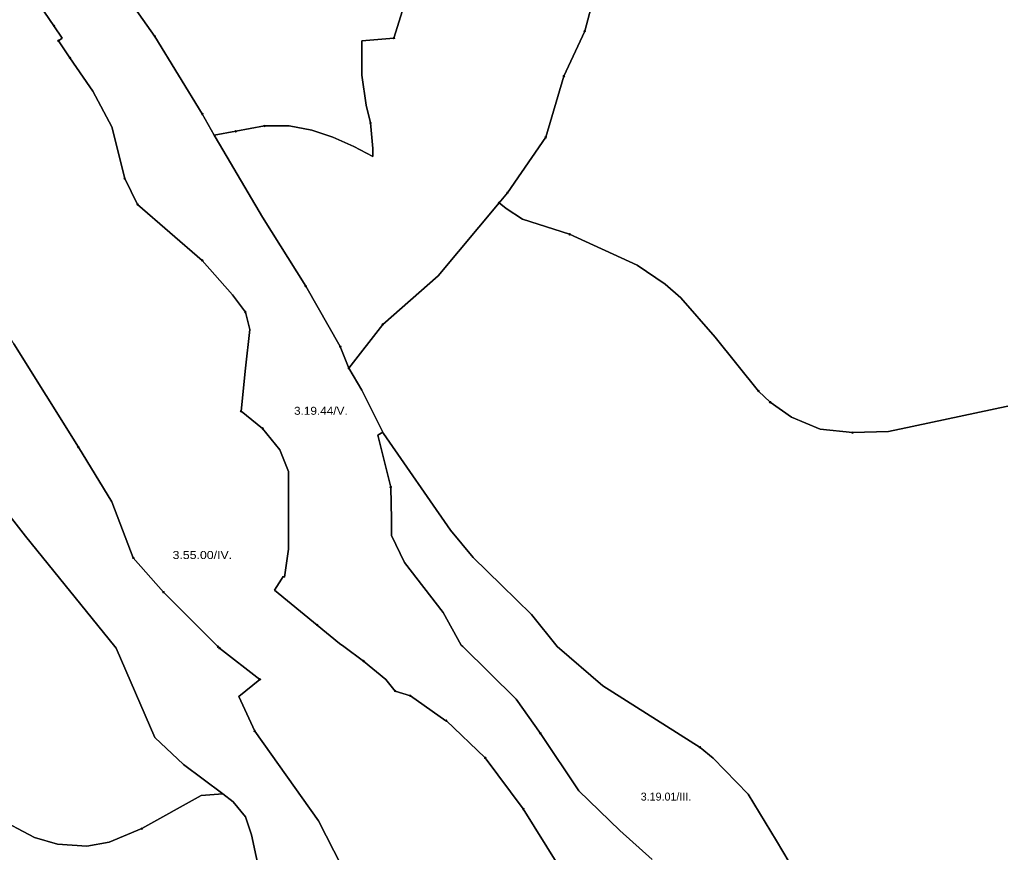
# Model space of a CAD drawing. Extents: x -650455 to -642254, y -1075222 to -1066610.
# Drawn here: x -646878 to -645652, y -1072257 to -1071216 of the extents above; entities that cross this region are included whole.
import ezdxf
from ezdxf.enums import TextEntityAlignment as Align

# ---------------------------------------------------------------- set-up
doc = ezdxf.new("R2010")
doc.units = 0
doc.header["$LTSCALE"] = 4
doc.header["$PDMODE"] = 32
doc.header["$PDSIZE"] = 2
for name, color, linetype, lineweight in [('1', 7, 'Continuous', 25), ('11', 7, 'Continuous', 13), ('12', 7, 'Continuous', 13), ('13', 7, 'Continuous', 13), ('14', 7, 'Continuous', 13), ('15', 7, 'Continuous', 13)]:
    doc.layers.add(name, color=color, linetype=linetype, lineweight=lineweight)
doc.layers.add('2', color=7, linetype='Continuous')

msp = doc.modelspace()

# ---------------------------------------------------------------- linework, layer by layer
at = {"layer": '1'}
for points in [[(-646154.372, -1071165.527), (-646171.706, -1071230.527), (-646197.706, -1071286.861), (-646220.456, -1071363.237), (-646268.124, -1071432.571), (-646278.639, -1071445.19), (-646354.791, -1071536.572), (-646424.125, -1071597.24), (-646466.433, -1071651.884), (-646477.206, -1071624.953), (-646520.295, -1071549.547), (-646574.157, -1071463.368), (-646628.018, -1071371.803), (-646634.506, -1071360.45), (-646607.539, -1071355.754), (-646571.854, -1071349.129), (-646541.062, -1071349.053), (-646512.831, -1071354.248), (-646486.255, -1071363.056), (-646460.282, -1071374.876)], [(-646190.5, -1071484.501), (-646249.5, -1071465.5), (-646270, -1071452.5), (-646278.639, -1071445.19), (-646268.124, -1071432.571), (-646220.456, -1071363.237), (-646197.706, -1071286.861), (-646171.706, -1071230.527), (-646154.372, -1071165.527)], [(-646393.156, -1071184.317), (-646410.042, -1071239.194), (-646450.275, -1071242.536), (-646450.275, -1071285.625), (-646444.889, -1071323.328), (-646439.373, -1071345.392), (-646436.341, -1071377.436), (-646436.341, -1071387.223), (-646460.282, -1071374.876), (-646486.255, -1071363.056), (-646512.831, -1071354.248), (-646541.062, -1071349.053), (-646571.854, -1071349.129), (-646607.539, -1071355.754), (-646634.506, -1071360.45), (-646649.563, -1071334.1), (-646708.811, -1071237.149), (-646743.712, -1071187.194)], [(-646743.712, -1071187.194), (-646708.811, -1071237.149), (-646649.563, -1071334.1), (-646634.506, -1071360.45), (-646628.018, -1071371.803), (-646574.157, -1071463.368), (-646520.295, -1071549.547), (-646477.206, -1071624.953), (-646466.433, -1071651.884), (-646450.126, -1071679.574), (-646423.791, -1071731.896), (-646430, -1071735.501), (-646414, -1071800.501), (-646413, -1071841.001), (-646413, -1071861.001), (-646397, -1071895), (-646348.5, -1071957.501)], [(-646460.282, -1071374.876), (-646436.341, -1071387.223), (-646436.341, -1071377.436), (-646439.373, -1071345.392), (-646444.889, -1071323.328), (-646450.275, -1071285.625), (-646450.275, -1071242.536), (-646410.042, -1071239.194), (-646393.156, -1071184.317)], [(-646786.429, -1071305.826), (-646790.183, -1071300.284), (-646814.876, -1071263.836), (-646829.299, -1071242.546), (-646824.502, -1071239.296), (-646834.862, -1071224.003), (-646859.12, -1071188.198)], [(-646859.12, -1071188.198), (-646834.862, -1071224.003), (-646824.502, -1071239.296), (-646829.299, -1071242.546), (-646814.876, -1071263.836), (-646790.183, -1071300.284), (-646786.429, -1071305.826), (-646762.673, -1071350.259), (-646746.514, -1071414.893), (-646730.355, -1071447.21), (-646649.563, -1071517.23), (-646611.86, -1071560.319), (-646595.701, -1071581.864), (-646590.315, -1071603.408), (-646595.701, -1071651.884), (-646601.087, -1071705.746), (-646574.157, -1071727.29), (-646552.612, -1071754.221), (-646541.84, -1071781.152), (-646541.84, -1071829.627), (-646541.84, -1071878.103), (-646546.839, -1071913.101), (-646548.5, -1071912.501), (-646550.686, -1071915.879)], [(-646175.5, -1072320), (-646248.5, -1072203), (-646296, -1072139.001), (-646345, -1072092.5), (-646345.4, -1072092.965), (-646389.5, -1072061.5), (-646408.5, -1072055.501), (-646420, -1072041), (-646448, -1072018.001), (-646472.545, -1072000), (-646478, -1071996), (-646506, -1071973.001), (-646559.5, -1071929.501), (-646550.686, -1071915.879), (-646548.5, -1071912.501), (-646546.839, -1071913.101), (-646541.84, -1071878.103), (-646541.84, -1071829.627), (-646541.84, -1071781.152), (-646552.612, -1071754.221), (-646574.157, -1071727.29), (-646601.087, -1071705.746), (-646595.701, -1071651.884), (-646590.315, -1071603.408), (-646595.701, -1071581.864), (-646611.86, -1071560.319), (-646649.563, -1071517.23), (-646730.355, -1071447.21), (-646746.514, -1071414.893), (-646762.673, -1071350.259), (-646786.429, -1071305.826)], [(-645908.5, -1072283), (-645932, -1072243), (-645967.5, -1072184.501), (-646011, -1072139.501), (-646027.5, -1072126), (-646149, -1072049), (-646206, -1072000), (-646238, -1071960), (-646275.5, -1071923), (-646311, -1071888.501), (-646339.5, -1071854.5), (-646423.033, -1071733.402), (-646423.791, -1071731.896), (-646450.126, -1071679.574), (-646466.433, -1071651.884), (-646424.125, -1071597.24), (-646354.791, -1071536.572), (-646278.639, -1071445.19), (-646270, -1071452.5), (-646249.5, -1071465.5), (-646190.5, -1071484.501), (-646106, -1071523), (-646071, -1071547), (-646051.5, -1071564.001), (-646008.5, -1071613.001), (-645954.5, -1071680.5), (-645940, -1071694.501), (-645913.5, -1071713), (-645877.5, -1071728), (-645837, -1071732.5), (-645792, -1071731.001), (-645762.5, -1071725), (-645619.5, -1071694.501)], [(-645619.5, -1071694.501), (-645762.5, -1071725), (-645792, -1071731.001), (-645837, -1071732.5), (-645877.5, -1071728), (-645913.5, -1071713), (-645940, -1071694.501), (-645954.5, -1071680.5), (-646008.5, -1071613.001), (-646051.5, -1071564.001), (-646071, -1071547), (-646106, -1071523), (-646190.5, -1071484.501)], [(-646447, -1072330.501), (-646504.5, -1072218), (-646584, -1072105.5), (-646604, -1072062.501), (-646577.5, -1072041), (-646628.018, -1072001.985), (-646630.002, -1072000), (-646698.038, -1071931.964), (-646735.742, -1071888.875), (-646762.673, -1071818.855), (-646804.415, -1071750.855), (-646885.208, -1071621.587)], [(-646885.208, -1071621.587), (-646804.415, -1071750.855), (-646762.673, -1071818.855), (-646735.742, -1071888.875), (-646698.038, -1071931.964), (-646630.002, -1072000), (-646628.018, -1072001.985), (-646577.5, -1072041), (-646604, -1072062.501), (-646584, -1072105.5), (-646504.5, -1072218), (-646447, -1072330.501)], [(-646087.5, -1072266.001), (-646128, -1072230), (-646179, -1072180.501), (-646227, -1072108.5), (-646257.5, -1072065.5), (-646323.97, -1072000), (-646326, -1071998.001), (-646348.5, -1071957.501), (-646397, -1071895), (-646413, -1071861.001), (-646413, -1071841.001), (-646414, -1071800.501), (-646430, -1071735.501), (-646423.791, -1071731.896), (-646423.033, -1071733.402), (-646339.5, -1071854.5), (-646311, -1071888.501), (-646275.5, -1071923), (-646238, -1071960), (-646206, -1072000), (-646149, -1072049), (-646027.5, -1072126), (-646011, -1072139.501), (-645967.5, -1072184.501), (-645932, -1072243), (-645908.5, -1072283)], [(-646611, -1072194), (-646624, -1072184.001), (-646673, -1072147.501), (-646709, -1072113.5), (-646757.286, -1072001.985), (-646758.889, -1072000), (-646870.396, -1071861.944), (-646929.643, -1071786.538)], [(-646929.643, -1071786.538), (-646870.396, -1071861.944), (-646758.889, -1072000), (-646757.286, -1072001.985), (-646709, -1072113.5), (-646673, -1072147.501), (-646624, -1072184.001), (-646651, -1072186), (-646725, -1072227.5), (-646766, -1072244.501), (-646794, -1072249.501), (-646830.5, -1072247), (-646859, -1072238.5), (-646908.5, -1072213.001)], [(-646550.686, -1071915.879), (-646559.5, -1071929.501), (-646506, -1071973.001), (-646478, -1071996), (-646472.545, -1072000), (-646448, -1072018.001), (-646420, -1072041), (-646408.5, -1072055.501), (-646389.5, -1072061.5), (-646345.4, -1072092.965), (-646345, -1072092.5), (-646296, -1072139.001), (-646248.5, -1072203), (-646175.5, -1072320), (-646120.5, -1072383.001), (-646020, -1072481), (-646013.29, -1072487.101)], [(-646348.5, -1071957.501), (-646326, -1071998.001), (-646323.97, -1072000), (-646257.5, -1072065.5), (-646227, -1072108.5), (-646179, -1072180.501), (-646128, -1072230), (-646087.5, -1072266.001)], [(-646908.5, -1072213.001), (-646859, -1072238.5), (-646830.5, -1072247), (-646794, -1072249.501), (-646766, -1072244.501), (-646725, -1072227.5), (-646651, -1072186), (-646624, -1072184.001), (-646611, -1072194), (-646595.5, -1072213.001), (-646588, -1072235.5), (-646576.5, -1072289.501), (-646559.5, -1072345.501), (-646540.5, -1072384), (-646514.5, -1072420.001), (-646470, -1072469.5), (-646420, -1072512.501), (-646392, -1072535), (-646381, -1072550.5), (-646346.5, -1072604.501), (-646329.469, -1072644.503), (-646334, -1072702.501), (-646348, -1072738.501), (-646368, -1072765.5)], [(-646576.5, -1072289.501), (-646588, -1072235.5), (-646595.5, -1072213.001), (-646611, -1072194)]]:
    msp.add_lwpolyline(points, dxfattribs=at)
at = {"layer": '11'}
for p, q in [((-646197.706, -1071286.861), (-646220.456, -1071363.237)), ((-646220.456, -1071363.237), (-646268.124, -1071432.571)), ((-646630.002, -1072000), (-646698.038, -1071931.964))]:
    msp.add_line(p, q, dxfattribs=at)
for points in [[(-646197.487, -1070763.107), (-646171.706, -1070831.857), (-646145.706, -1070901.191), (-646141.372, -1070996.525), (-646145.706, -1071100.526), (-646154.372, -1071165.527), (-646171.706, -1071230.527), (-646197.706, -1071286.861)], [(-646268.124, -1071432.571), (-646278.639, -1071445.19), (-646270, -1071452.5), (-646249.5, -1071465.5), (-646190.5, -1071484.501)], [(-646698.038, -1071931.964), (-646735.742, -1071888.875), (-646762.673, -1071818.855), (-646804.415, -1071750.855), (-646885.208, -1071621.587), (-646992.931, -1071454.616)], [(-645954.5, -1071680.5), (-646008.5, -1071613.001), (-646051.5, -1071564.001), (-646071, -1071547), (-646106, -1071523), (-646190.5, -1071484.501), (-646249.5, -1071465.5), (-646270, -1071452.5), (-646278.639, -1071445.19), (-646354.791, -1071536.572), (-646424.125, -1071597.24), (-646466.433, -1071651.884)], [(-646190.5, -1071484.501), (-646106, -1071523), (-646071, -1071547), (-646051.5, -1071564.001), (-646008.5, -1071613.001), (-645954.5, -1071680.5), (-645940, -1071694.501)], [(-646466.433, -1071651.884), (-646450.126, -1071679.574), (-646423.791, -1071731.896), (-646423.033, -1071733.402), (-646339.5, -1071854.5), (-646311, -1071888.501), (-646275.5, -1071923), (-646238, -1071960), (-646206, -1072000), (-646149, -1072049), (-646027.5, -1072126)], [(-645837, -1071732.5), (-645792, -1071731.001), (-645762.5, -1071725), (-645619.5, -1071694.501), (-645493, -1071675.001), (-645451, -1071667.001), (-645411, -1071663), (-645381.5, -1071666.001), (-645306, -1071694.501)], [(-645493, -1071675.001), (-645619.5, -1071694.501), (-645762.5, -1071725), (-645792, -1071731.001), (-645837, -1071732.5), (-645877.5, -1071728), (-645913.5, -1071713), (-645940, -1071694.501), (-645954.5, -1071680.5)], [(-645940, -1071694.501), (-645913.5, -1071713), (-645877.5, -1071728), (-645837, -1071732.5)], [(-646908.5, -1072213.001), (-646859, -1072238.5), (-646830.5, -1072247), (-646794, -1072249.501), (-646766, -1072244.501), (-646725, -1072227.5), (-646651, -1072186), (-646624, -1072184.001), (-646673, -1072147.501), (-646709, -1072113.5), (-646757.286, -1072001.985), (-646758.889, -1072000), (-646870.396, -1071861.944), (-646929.643, -1071786.538)], [(-646929.643, -1071786.538), (-646870.396, -1071861.944), (-646758.889, -1072000), (-646757.286, -1072001.985), (-646709, -1072113.5), (-646673, -1072147.501), (-646624, -1072184.001), (-646611, -1072194), (-646595.5, -1072213.001), (-646588, -1072235.5), (-646576.5, -1072289.501), (-646559.5, -1072345.501), (-646540.5, -1072384)], [(-646584, -1072105.5), (-646604, -1072062.501), (-646577.5, -1072041), (-646628.018, -1072001.985), (-646630.002, -1072000)], [(-646725, -1072227.5), (-646766, -1072244.501), (-646794, -1072249.501), (-646830.5, -1072247), (-646859, -1072238.5), (-646908.5, -1072213.001), (-646971, -1072165.5), (-647106.5, -1072039.5)], [(-646346.5, -1072527.501), (-646337, -1072520.001), (-646337, -1072506), (-646381, -1072447.501), (-646419.5, -1072388.5), (-646447, -1072330.501), (-646504.5, -1072218), (-646584, -1072105.5)], [(-646027.5, -1072126), (-646011, -1072139.501), (-645967.5, -1072184.501), (-645932, -1072243), (-645908.5, -1072283), (-645884.5, -1072309.501), (-645854, -1072327), (-645788.5, -1072351.001), (-645718.5, -1072394.001), (-645697, -1072391.501), (-645594, -1072384.5), (-645567.5, -1072387.001), (-645560, -1072390.001), (-645550.5, -1072338.001), (-645549, -1072189.5), (-645544.5, -1072153.5), (-645532, -1072135.501), (-645510.5, -1072118.5), (-645474.5, -1072111.501), (-645421, -1072113), (-645398, -1072117), (-645373.5, -1072126), (-645338.5, -1072147.001)], [(-646559.5, -1072345.501), (-646576.5, -1072289.501), (-646588, -1072235.5), (-646595.5, -1072213.001), (-646611, -1072194), (-646624, -1072184.001), (-646651, -1072186), (-646725, -1072227.5)]]:
    msp.add_lwpolyline(points, dxfattribs=at)
for p in [(-646197.706, -1071286.861), (-646220.456, -1071363.237), (-646268.124, -1071432.571), (-646190.5, -1071484.501), (-646466.433, -1071651.884), (-645954.5, -1071680.5), (-645940, -1071694.501), (-645837, -1071732.5), (-646698.038, -1071931.964), (-646630.002, -1072000), (-646584, -1072105.5), (-646027.5, -1072126), (-646725, -1072227.5)]:
    msp.add_point(p, dxfattribs=at)
at = {"layer": '12'}
for p, q in [((-646197.706, -1071286.861), (-646171.706, -1071230.527)), ((-646278.639, -1071445.19), (-646268.124, -1071432.571))]:
    msp.add_line(p, q, dxfattribs=at)
for points in [[(-646171.706, -1071230.527), (-646154.372, -1071165.527), (-646145.706, -1071100.526), (-646141.372, -1070996.525), (-646145.706, -1070901.191), (-646171.706, -1070831.857), (-646197.487, -1070763.107), (-646197.659, -1070749.898)], [(-646396.096, -1071025.528), (-646393.156, -1071184.317), (-646410.042, -1071239.194)], [(-646410.042, -1071239.194), (-646450.275, -1071242.536), (-646450.275, -1071285.625), (-646444.889, -1071323.328), (-646439.373, -1071345.392)], [(-646268.124, -1071432.571), (-646220.456, -1071363.237), (-646197.706, -1071286.861)], [(-646439.373, -1071345.392), (-646436.341, -1071377.436), (-646436.341, -1071387.223), (-646460.282, -1071374.876), (-646486.255, -1071363.056), (-646512.831, -1071354.248), (-646541.062, -1071349.053), (-646571.854, -1071349.129), (-646607.539, -1071355.754), (-646634.506, -1071360.45), (-646628.018, -1071371.803), (-646574.157, -1071463.368), (-646520.295, -1071549.547), (-646477.206, -1071624.953)], [(-646424.125, -1071597.24), (-646354.791, -1071536.572), (-646278.639, -1071445.19)], [(-646477.206, -1071624.953), (-646466.433, -1071651.884), (-646424.125, -1071597.24)]]:
    msp.add_lwpolyline(points, dxfattribs=at)
for p in [(-646171.706, -1071230.527), (-646410.042, -1071239.194), (-646197.706, -1071286.861), (-646439.373, -1071345.392), (-646268.124, -1071432.571), (-646278.639, -1071445.19), (-646424.125, -1071597.24), (-646477.206, -1071624.953)]:
    msp.add_point(p, dxfattribs=at)
at = {"layer": '13'}
for p, q in [((-646708.811, -1071237.149), (-646649.563, -1071334.1)), ((-646607.539, -1071355.754), (-646571.854, -1071349.129))]:
    msp.add_line(p, q, dxfattribs=at)
for points in [[(-646677.628, -1070751.147), (-646699.295, -1070738.147), (-646729.628, -1070720.814), (-646751.296, -1070768.481), (-646768.629, -1070811.815), (-646799.029, -1070883.683), (-646815.187, -1070905.227), (-646831.346, -1070932.158), (-646869.049, -1070964.475), (-646804.415, -1071034.495), (-646782.712, -1071061.526), (-646782.712, -1071100.526), (-646769.712, -1071135.193), (-646743.712, -1071187.194), (-646708.811, -1071237.149)], [(-646410.042, -1071239.194), (-646393.156, -1071184.317), (-646396.096, -1071025.528), (-646392.694, -1071012.768)], [(-646571.854, -1071349.129), (-646541.062, -1071349.053), (-646512.831, -1071354.248), (-646486.255, -1071363.056), (-646460.282, -1071374.876), (-646436.341, -1071387.223), (-646436.341, -1071377.436), (-646439.373, -1071345.392), (-646444.889, -1071323.328), (-646450.275, -1071285.625), (-646450.275, -1071242.536), (-646410.042, -1071239.194)], [(-646649.563, -1071334.1), (-646634.506, -1071360.45), (-646607.539, -1071355.754)], [(-645908.5, -1072283), (-645932, -1072243), (-645967.5, -1072184.501), (-646011, -1072139.501), (-646027.5, -1072126), (-646149, -1072049), (-646206, -1072000), (-646238, -1071960), (-646275.5, -1071923), (-646311, -1071888.501), (-646339.5, -1071854.5), (-646423.033, -1071733.402), (-646423.791, -1071731.896), (-646430, -1071735.501), (-646414, -1071800.501), (-646413, -1071841.001), (-646413, -1071861.001), (-646397, -1071895), (-646348.5, -1071957.501), (-646326, -1071998.001), (-646323.97, -1072000), (-646257.5, -1072065.5), (-646227, -1072108.5), (-646179, -1072180.501), (-646128, -1072230), (-646087.5, -1072266.001)]]:
    msp.add_lwpolyline(points, dxfattribs=at)
for p in [(-646708.811, -1071237.149), (-646410.042, -1071239.194), (-646649.563, -1071334.1), (-646607.539, -1071355.754), (-646571.854, -1071349.129)]:
    msp.add_point(p, dxfattribs=at)
at = {"layer": '14'}
for p, q in [((-646885.208, -1071621.587), (-646804.415, -1071750.855)), ((-646628.018, -1072001.985), (-646577.5, -1072041)), ((-646296, -1072139.001), (-646345, -1072092.5))]:
    msp.add_line(p, q, dxfattribs=at)
for points in [[(-646829.299, -1071242.546), (-646824.502, -1071239.296), (-646834.862, -1071224.003), (-646859.12, -1071188.198), (-646868.599, -1071172.329), (-646871.388, -1071167.008)], [(-646746.514, -1071414.893), (-646762.673, -1071350.259), (-646786.429, -1071305.826), (-646790.183, -1071300.284), (-646814.876, -1071263.836), (-646829.299, -1071242.546)], [(-646595.701, -1071581.864), (-646611.86, -1071560.319), (-646649.563, -1071517.23), (-646730.355, -1071447.21), (-646746.514, -1071414.893)], [(-646601.087, -1071705.746), (-646595.701, -1071651.884), (-646590.315, -1071603.408), (-646595.701, -1071581.864)], [(-646448, -1072018.001), (-646472.545, -1072000), (-646478, -1071996), (-646506, -1071973.001), (-646559.5, -1071929.501), (-646550.686, -1071915.879), (-646548.5, -1071912.501), (-646546.839, -1071913.101), (-646541.84, -1071878.103), (-646541.84, -1071829.627), (-646541.84, -1071781.152), (-646552.612, -1071754.221), (-646574.157, -1071727.29), (-646601.087, -1071705.746)], [(-646804.415, -1071750.855), (-646762.673, -1071818.855), (-646735.742, -1071888.875)], [(-646735.742, -1071888.875), (-646698.038, -1071931.964), (-646630.002, -1072000), (-646628.018, -1072001.985)], [(-646345, -1072092.5), (-646345.4, -1072092.965), (-646389.5, -1072061.5), (-646408.5, -1072055.501), (-646420, -1072041), (-646448, -1072018.001)], [(-646577.5, -1072041), (-646604, -1072062.501), (-646584, -1072105.5), (-646504.5, -1072218), (-646447, -1072330.501), (-646419.5, -1072388.5), (-646381, -1072447.501)], [(-646175.5, -1072320), (-646248.5, -1072203), (-646296, -1072139.001)]]:
    msp.add_lwpolyline(points, dxfattribs=at)
for p in [(-646829.299, -1071242.546), (-646746.514, -1071414.893), (-646595.701, -1071581.864), (-646601.087, -1071705.746), (-646804.415, -1071750.855), (-646735.742, -1071888.875), (-646628.018, -1072001.985), (-646448, -1072018.001), (-646577.5, -1072041), (-646345, -1072092.5), (-646296, -1072139.001)]:
    msp.add_point(p, dxfattribs=at)
at = {"layer": '15'}
for p, q in [((-646730.355, -1071447.21), (-646649.563, -1071517.23)), ((-646408.5, -1072055.501), (-646389.5, -1072061.5))]:
    msp.add_line(p, q, dxfattribs=at)
for points in [[(-646868.599, -1071172.329), (-646859.12, -1071188.198), (-646834.862, -1071224.003)], [(-646649.563, -1071334.1), (-646708.811, -1071237.149), (-646743.712, -1071187.194)], [(-646834.862, -1071224.003), (-646824.502, -1071239.296), (-646829.299, -1071242.546), (-646814.876, -1071263.836)], [(-646814.876, -1071263.836), (-646790.183, -1071300.284), (-646786.429, -1071305.826), (-646762.673, -1071350.259), (-646746.514, -1071414.893), (-646730.355, -1071447.21)], [(-646520.295, -1071549.547), (-646574.157, -1071463.368), (-646628.018, -1071371.803), (-646634.506, -1071360.45), (-646649.563, -1071334.1)], [(-646649.563, -1071517.23), (-646611.86, -1071560.319), (-646595.701, -1071581.864), (-646590.315, -1071603.408), (-646595.701, -1071651.884), (-646601.087, -1071705.746), (-646574.157, -1071727.29)], [(-646414, -1071800.501), (-646430, -1071735.501), (-646423.791, -1071731.896), (-646450.126, -1071679.574), (-646466.433, -1071651.884), (-646477.206, -1071624.953), (-646520.295, -1071549.547)], [(-646574.157, -1071727.29), (-646552.612, -1071754.221), (-646541.84, -1071781.152), (-646541.84, -1071829.627), (-646541.84, -1071878.103), (-646546.839, -1071913.101)], [(-646227, -1072108.5), (-646257.5, -1072065.5), (-646323.97, -1072000), (-646326, -1071998.001), (-646348.5, -1071957.501), (-646397, -1071895), (-646413, -1071861.001), (-646413, -1071841.001), (-646414, -1071800.501)], [(-646546.839, -1071913.101), (-646548.5, -1071912.501), (-646550.686, -1071915.879), (-646559.5, -1071929.501), (-646506, -1071973.001)], [(-646506, -1071973.001), (-646478, -1071996), (-646472.545, -1072000), (-646448, -1072018.001), (-646420, -1072041), (-646408.5, -1072055.501)], [(-646389.5, -1072061.5), (-646345.4, -1072092.965), (-646345, -1072092.5), (-646296, -1072139.001), (-646248.5, -1072203)], [(-646087.5, -1072266.001), (-646128, -1072230), (-646179, -1072180.501), (-646227, -1072108.5)], [(-646248.5, -1072203), (-646175.5, -1072320), (-646120.5, -1072383.001), (-646020, -1072481), (-646013.29, -1072487.101), (-646005.6, -1072481.541), (-645979.711, -1072449.972), (-645952, -1072479.501), (-645903.5, -1072547), (-645924, -1072572.501)]]:
    msp.add_lwpolyline(points, dxfattribs=at)
for p in [(-646834.862, -1071224.003), (-646814.876, -1071263.836), (-646649.563, -1071334.1), (-646730.355, -1071447.21), (-646649.563, -1071517.23), (-646520.295, -1071549.547), (-646574.157, -1071727.29), (-646414, -1071800.501), (-646506, -1071973.001), (-646408.5, -1072055.501), (-646389.5, -1072061.5), (-646227, -1072108.5), (-646248.5, -1072203)]:
    msp.add_point(p, dxfattribs=at)

# ---------------------------------------------------------------- texts
at = {"layer": '2'}
for s, width, p in [('3.19.44/V.', 1.1, (-646501.37, -1071710.19)), ('3.55.00/IV.', 1.15, (-646649.471, -1071890.494))]:
    msp.add_text(s, height=10, dxfattribs=dict(at, width=width)).set_placement(p, align=Align.CENTER)
msp.add_text('3.19.01/III.', height=10, dxfattribs=at).set_placement((-646070.114, -1072192.522), align=Align.CENTER)

doc.saveas('drawing.dxf')
